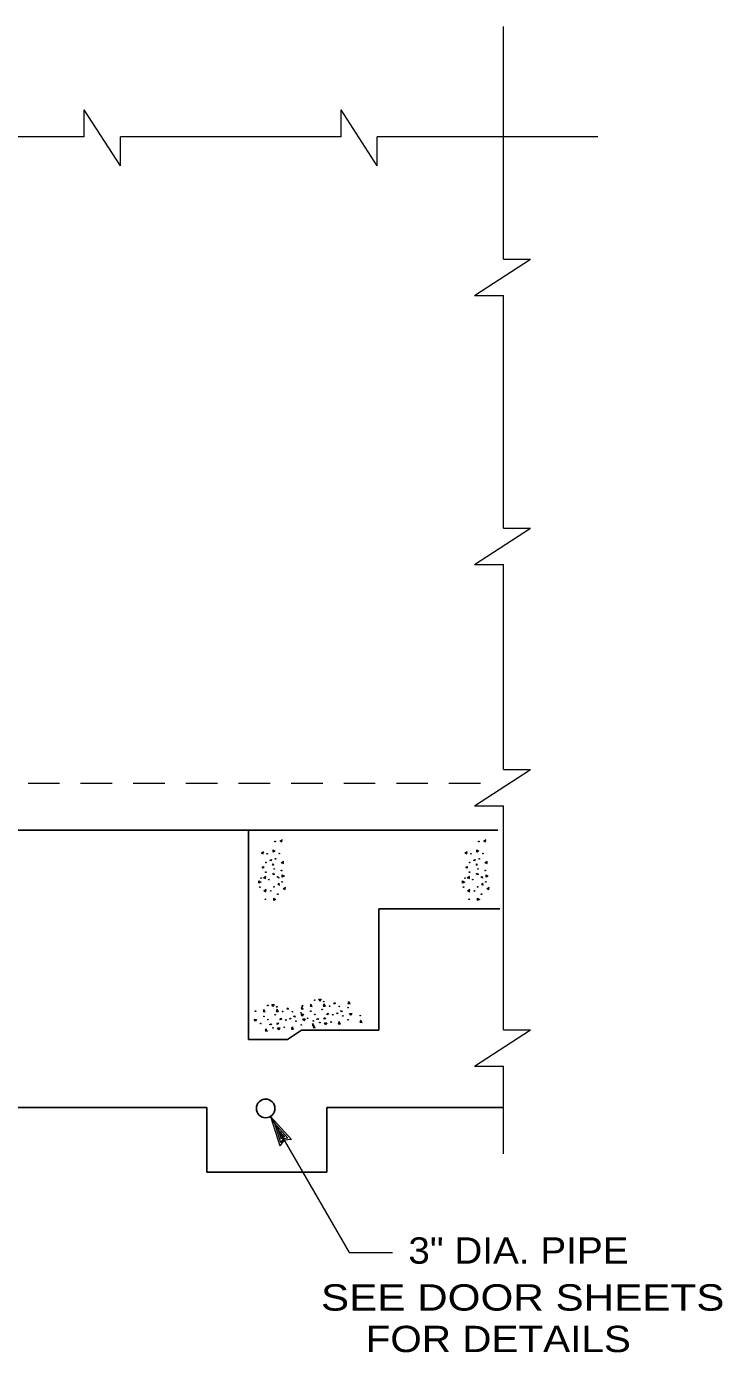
# Model space of a CAD drawing. Extents: x -28.1 to 13.9, y -16.1 to 13.9.
# Drawn here: x -14.93 to -11.62, y -7.32 to -1.03 of the extents above; entities that cross this region are included whole.
import ezdxf
from ezdxf.enums import TextEntityAlignment as Align

# ---------------------------------------------------------------- set-up
doc = ezdxf.new("R2010")
doc.units = 0
doc.header["$LTSCALE"] = 0.05
doc.linetypes.add('MEDIUM_DASHED', pattern=[4.5, 3, -1.5])
doc.layers.add('1', color=7, linetype='Continuous', lineweight=13)
doc.layers.add('2', color=7, linetype='Continuous', lineweight=13)

msp = doc.modelspace()

# ---------------------------------------------------------------- linework, layer by layer
at = {"layer": '1'}
for p, q in [((-12.65904, -2.13331), (-12.65904, -1.02831)), ((-14.65104, -1.55131), (-14.65104, -1.42331)), ((-14.47904, -1.68931), (-14.65104, -1.42331)), ((-13.43104, -1.55131), (-13.43104, -1.42331)), ((-13.25904, -1.68931), (-13.43104, -1.42331)), ((-14.65104, -1.55131), (-15.71504, -1.55131)), ((-14.47904, -1.68931), (-14.47904, -1.55131)), ((-13.43104, -1.55131), (-14.47904, -1.55131)), ((-13.25904, -1.68931), (-13.25904, -1.55131)), ((-12.21104, -1.55131), (-13.25904, -1.55131)), ((-12.79704, -2.30531), (-12.53104, -2.13331)), ((-12.65904, -2.13331), (-12.53104, -2.13331)), ((-12.79704, -2.30531), (-12.65904, -2.30531)), ((-12.65904, -3.41031), (-12.65904, -2.30531)), ((-12.79704, -3.58231), (-12.53104, -3.41031)), ((-12.65904, -3.41031), (-12.53104, -3.41031)), ((-12.79704, -3.58231), (-12.65904, -3.58231)), ((-12.65904, -4.55631), (-12.65904, -3.58231)), ((-12.79704, -4.72831), (-12.53104, -4.55631)), ((-12.65904, -4.55631), (-12.53104, -4.55631)), ((-12.79704, -4.72831), (-12.65904, -4.72831)), ((-12.65904, -5.79231), (-12.65904, -4.72831)), ((-12.79704, -5.96431), (-12.53104, -5.79231)), ((-12.65904, -5.79231), (-12.53104, -5.79231)), ((-12.79704, -5.96431), (-12.65904, -5.96431)), ((-12.65904, -6.38131), (-12.65904, -5.96431)), ((-13.76604, -6.20331), (-13.66704, -6.31231)), ((-13.76604, -6.20331), (-13.72104, -6.34331)), ((-13.74704, -6.23531), (-13.68304, -6.30631)), ((-13.74704, -6.23531), (-13.71804, -6.32631)), ((-13.72904, -6.26631), (-13.71504, -6.31031)), ((-13.72904, -6.26631), (-13.69804, -6.30031)), ((-13.70504, -6.30931), (-13.71804, -6.32631)), ((-13.70904, -6.30231), (-13.71504, -6.31031)), ((-13.69804, -6.30031), (-13.70904, -6.30231)), ((-13.68304, -6.30631), (-13.70504, -6.30931))]:
    msp.add_line(p, q, dxfattribs=at)
at = {"layer": '1', "linetype": 'MEDIUM_DASHED'}
msp.add_line((-20.41804, -4.62131), (-12.68204, -4.62131), dxfattribs=at)
at = {"layer": '1', "lineweight": 25}
for p, q in [((-21.29204, -4.84331), (-12.68604, -4.84331)), ((-13.87004, -5.83731), (-13.87004, -4.84331)), ((-13.25204, -5.79331), (-13.25204, -5.21731)), ((-13.25204, -5.21731), (-12.67704, -5.21731)), ((-13.68504, -5.83731), (-13.87004, -5.83731)), ((-13.61904, -5.79331), (-13.68504, -5.83731)), ((-13.25204, -5.79331), (-13.61904, -5.79331)), ((-14.06804, -6.46731), (-14.06804, -6.16031)), ((-13.49904, -6.46731), (-13.49904, -6.16031)), ((-13.49904, -6.16031), (-12.65904, -6.16031)), ((-13.49904, -6.46731), (-14.06804, -6.46731))]:
    msp.add_line(p, q, dxfattribs=at)
msp.add_lwpolyline([(-17.45804, -6.46731), (-17.45804, -6.16031), (-14.06804, -6.16031)], dxfattribs=at)
at = {"layer": '1'}
for points in [[(-13.76604, -6.20331), (-13.39304, -6.84931), (-13.18604, -6.84931)], [(-13.66704, -6.31231), (-13.70104, -6.31631), (-13.72104, -6.34331)]]:
    msp.add_lwpolyline(points, dxfattribs=at)
at = {"layer": '1', "lineweight": 25}
msp.add_circle((-13.78904, -6.16531), 0.04428, dxfattribs=at)
at = {"layer": '2'}
for p, q in [((-13.80104, -5.02431), (-13.80604, -5.01831)), ((-12.83304, -5.02431), (-12.83804, -5.01831)), ((-13.46604, -5.66731), (-13.46004, -5.66231)), ((-13.68904, -5.69231), (-13.68304, -5.68731))]:
    msp.add_line(p, q, dxfattribs=at)
for points in [[(-13.72204, -4.89431), (-13.71204, -4.89931), (-13.71104, -4.88931), (-13.72204, -4.89631)], [(-12.75404, -4.89431), (-12.74404, -4.89931), (-12.74304, -4.88931), (-12.75404, -4.89631)], [(-13.81104, -4.95131), (-13.80104, -4.95631), (-13.80004, -4.94631), (-13.81104, -4.95431)], [(-13.74604, -4.94331), (-13.75404, -4.94831), (-13.75404, -4.93731), (-13.74404, -4.94331)], [(-12.84304, -4.95131), (-12.83304, -4.95631), (-12.83204, -4.94631), (-12.84304, -4.95431)], [(-12.77804, -4.94331), (-12.78604, -4.94831), (-12.78604, -4.93731), (-12.77604, -4.94331)], [(-13.80604, -5.01831), (-13.79904, -5.01631), (-13.79904, -5.02431)], [(-13.76604, -4.99131), (-13.76804, -4.98631), (-13.76204, -4.98331), (-13.76504, -4.99131)], [(-13.75304, -5.01131), (-13.75704, -5.00831), (-13.75304, -5.00331), (-13.75204, -5.01031)], [(-13.71504, -4.99731), (-13.70504, -5.00231), (-13.70404, -4.99231), (-13.71504, -5.00031)], [(-12.83804, -5.01831), (-12.83104, -5.01631), (-12.83104, -5.02431)], [(-12.79804, -4.99131), (-12.80004, -4.98631), (-12.79404, -4.98331), (-12.79704, -4.99131)], [(-12.78504, -5.01131), (-12.78904, -5.00831), (-12.78504, -5.00331), (-12.78404, -5.01031)], [(-12.74704, -4.99731), (-12.73704, -5.00231), (-12.73604, -4.99231), (-12.74704, -5.00031)], [(-13.81304, -5.09031), (-13.82204, -5.09531), (-13.82204, -5.08431), (-13.81104, -5.09031)], [(-13.79904, -5.06931), (-13.78904, -5.07431), (-13.78804, -5.06331), (-13.79904, -5.07131)], [(-13.72704, -5.10431), (-13.73004, -5.09931), (-13.72704, -5.09531), (-13.72504, -5.10731)], [(-13.70104, -5.06231), (-13.71004, -5.06731), (-13.71004, -5.05631), (-13.70004, -5.06231)], [(-12.84504, -5.09031), (-12.85404, -5.09531), (-12.85404, -5.08431), (-12.84304, -5.09031)], [(-12.83104, -5.06931), (-12.82104, -5.07431), (-12.82004, -5.06331), (-12.83104, -5.07131)], [(-12.75904, -5.10431), (-12.76204, -5.09931), (-12.75904, -5.09531), (-12.75704, -5.10731)], [(-12.73304, -5.06231), (-12.74204, -5.06731), (-12.74204, -5.05631), (-12.73204, -5.06231)], [(-13.79804, -5.13131), (-13.78804, -5.13631), (-13.78704, -5.12631), (-13.79804, -5.13431)], [(-13.70604, -5.12131), (-13.69604, -5.12631), (-13.69504, -5.11631), (-13.70604, -5.12431)], [(-12.83004, -5.13131), (-12.82004, -5.13631), (-12.81904, -5.12631), (-12.83004, -5.13431)], [(-12.73804, -5.12131), (-12.72804, -5.12631), (-12.72704, -5.11631), (-12.73804, -5.12431)], [(-13.74204, -5.17331), (-13.75004, -5.17831), (-13.75004, -5.16731), (-13.74004, -5.17331)], [(-12.77404, -5.17331), (-12.78204, -5.17831), (-12.78204, -5.16731), (-12.77204, -5.17331)], [(-13.53204, -5.65531), (-13.53704, -5.64631), (-13.52604, -5.64631), (-13.53204, -5.65731)], [(-13.46004, -5.66231), (-13.45804, -5.66931), (-13.46604, -5.66931)], [(-13.39304, -5.65731), (-13.39804, -5.66731), (-13.38804, -5.66831), (-13.39604, -5.65731)], [(-13.79604, -5.69531), (-13.80104, -5.70531), (-13.79104, -5.70631), (-13.79904, -5.69531)], [(-13.75504, -5.68031), (-13.76004, -5.67131), (-13.74904, -5.67131), (-13.75504, -5.68231)], [(-13.73404, -5.69431), (-13.73904, -5.70431), (-13.72804, -5.70531), (-13.73604, -5.69431)], [(-13.68304, -5.68731), (-13.68104, -5.69431), (-13.68904, -5.69431)], [(-13.65604, -5.72731), (-13.65104, -5.72531), (-13.64804, -5.73131), (-13.65604, -5.72831)], [(-13.61604, -5.68231), (-13.62104, -5.69231), (-13.61104, -5.69331), (-13.61904, -5.68231)], [(-13.61504, -5.72631), (-13.62004, -5.71831), (-13.60904, -5.71831), (-13.61504, -5.72831)], [(-13.57304, -5.67031), (-13.57804, -5.68031), (-13.56804, -5.68131), (-13.57604, -5.67031)], [(-13.51104, -5.66931), (-13.51604, -5.67931), (-13.50504, -5.68031), (-13.51304, -5.66931)], [(-13.45304, -5.71531), (-13.45004, -5.71131), (-13.44504, -5.71531), (-13.45204, -5.71631)], [(-13.43304, -5.70231), (-13.42804, -5.70031), (-13.42504, -5.70631), (-13.43304, -5.70331)], [(-13.38504, -5.72231), (-13.39004, -5.71431), (-13.37904, -5.71431), (-13.38504, -5.72431)], [(-13.83804, -5.75131), (-13.84304, -5.74331), (-13.83204, -5.74331), (-13.83804, -5.75331)], [(-13.78604, -5.78731), (-13.79104, -5.79731), (-13.78104, -5.79831), (-13.78904, -5.78731)], [(-13.76904, -5.76631), (-13.76404, -5.76331), (-13.76004, -5.76631), (-13.77204, -5.76831)], [(-13.72704, -5.79231), (-13.73204, -5.78331), (-13.72104, -5.78331), (-13.72704, -5.79331)], [(-13.67604, -5.74031), (-13.67304, -5.73631), (-13.66804, -5.74031), (-13.67504, -5.74131)], [(-13.66204, -5.77831), (-13.66704, -5.78831), (-13.65704, -5.78931), (-13.66504, -5.77831)], [(-13.60804, -5.74731), (-13.61304, -5.73931), (-13.60204, -5.73931), (-13.60804, -5.74931)], [(-13.56304, -5.76231), (-13.56804, -5.77231), (-13.55804, -5.77331), (-13.56604, -5.76231)], [(-13.55904, -5.77131), (-13.56404, -5.78131), (-13.55404, -5.78231), (-13.56104, -5.77131)], [(-13.54604, -5.74131), (-13.54104, -5.73831), (-13.53704, -5.74131), (-13.54904, -5.74331)], [(-13.50404, -5.76731), (-13.50904, -5.75831), (-13.49804, -5.75831), (-13.50404, -5.76831)], [(-13.43904, -5.75331), (-13.44404, -5.76331), (-13.43404, -5.76431), (-13.44204, -5.75331)], [(-13.33604, -5.74631), (-13.34104, -5.75631), (-13.33104, -5.75731), (-13.33804, -5.74631)]]:
    msp.add_lwpolyline(points, dxfattribs=at)
for points in [[(-13.74804, -5.05631), (-13.75704, -5.05131), (-13.75104, -5.04831)], [(-13.72704, -5.07131), (-13.73504, -5.06631), (-13.72904, -5.06331)], [(-12.78004, -5.05631), (-12.78904, -5.05131), (-12.78304, -5.04831)], [(-12.75904, -5.07131), (-12.76704, -5.06631), (-12.76104, -5.06331)], [(-13.49804, -5.72031), (-13.49304, -5.71131), (-13.49004, -5.71731)], [(-13.73604, -5.76631), (-13.73104, -5.75831), (-13.72804, -5.76431)], [(-13.72104, -5.74531), (-13.71604, -5.73631), (-13.71304, -5.74231)], [(-13.51304, -5.74131), (-13.50804, -5.73331), (-13.50504, -5.73931)]]:
    msp.add_lwpolyline(points, close=True, dxfattribs=at)
for centre in [(-13.74392, -4.89781), (-12.77592, -4.89781), (-13.78167, -4.95606), (-13.72442, -4.95506), (-12.81367, -4.95606), (-12.75642, -4.95506), (-13.78742, -4.99731), (-13.74792, -5.02831), (-13.74217, -4.98031), (-13.71342, -5.03581), (-12.81942, -4.99731), (-12.77992, -5.02831), (-12.77417, -4.98031), (-12.74542, -5.03581), (-13.81017, -5.07131), (-13.78842, -5.04356), (-13.77317, -5.07881), (-13.71092, -5.08981), (-12.84217, -5.07131), (-12.82042, -5.04356), (-12.80517, -5.07881), (-12.74292, -5.08981), (-13.81692, -5.11406), (-13.76492, -5.13256), (-13.74967, -5.11331), (-13.73117, -5.14781), (-12.84892, -5.11406), (-12.79692, -5.13256), (-12.78167, -5.11331), (-12.76317, -5.14781), (-13.79017, -5.17231), (-12.82217, -5.17231), (-13.55579, -5.65144), (-13.51304, -5.65819), (-13.83704, -5.70319), (-13.79729, -5.72844), (-13.77879, -5.67644), (-13.74354, -5.72019), (-13.73604, -5.68319), (-13.70829, -5.70494), (-13.66204, -5.70594), (-13.62079, -5.71169), (-13.61404, -5.67819), (-13.57429, -5.70344), (-13.55504, -5.71869), (-13.52054, -5.69519), (-13.48529, -5.67994), (-13.47004, -5.72044), (-13.43904, -5.68094), (-13.42204, -5.72619), (-13.39779, -5.68669), (-13.33954, -5.72444), (-13.81254, -5.76219), (-13.77804, -5.74369), (-13.75454, -5.78244), (-13.70054, -5.77994), (-13.69304, -5.74544), (-13.64504, -5.75119), (-13.61979, -5.76894), (-13.58954, -5.73719), (-13.56254, -5.74944), (-13.53154, -5.75744), (-13.47754, -5.75494), (-13.39679, -5.74394)]:
    msp.add_circle(centre, 0.00162, dxfattribs=at)

# ---------------------------------------------------------------- texts
at = {"layer": '1', "width": 1.1}
msp.add_text('3" DIA. PIPE', height=0.125, dxfattribs=at).set_placement((-13.11104, -6.90231))
at = {"layer": '1'}
for s, width, p in [('SEE DOOR SHEETS ', 1.2, (-12.53988, -7.12531)), ('FOR DETAILS', 1.15, (-12.68393, -7.32231))]:
    msp.add_text(s, height=0.125, dxfattribs=dict(at, width=width)).set_placement(p, align=Align.CENTER)

doc.saveas('drawing.dxf')
